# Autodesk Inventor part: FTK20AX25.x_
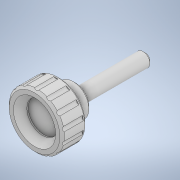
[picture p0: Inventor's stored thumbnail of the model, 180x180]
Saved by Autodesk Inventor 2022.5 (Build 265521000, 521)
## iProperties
Created: 2023-10
Part Number: FTK20AX25.x_
Material: 一般
Document SubType Name: Modeling
Designer: ImaoCorp
Density: 1 g/cm^3
Appearance: 既定
Sending System: SOLIDWORKS 2021-2021301
MC: AMD64
MC_MODEL: Intel64 Family 6 Model 60 Stepping 3, GenuineIntel
OS: Windows_NT
FRU: Parasolid Version 32.1, build 255,  1- 1-2021
FORMAT: text
GUISE: transmit
KEY: FTK20AX25
FILE: FTK20AX25.x_t
DATE: Tue Oct 17 11:07:21 2023
Author: ImaoCorp
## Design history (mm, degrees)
feature "Base1"
node "ソリッド1"
